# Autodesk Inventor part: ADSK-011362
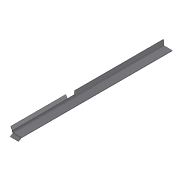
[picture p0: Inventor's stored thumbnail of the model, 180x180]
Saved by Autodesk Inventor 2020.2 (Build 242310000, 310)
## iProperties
Created: 1999-12
Part Number: ADSK-011362
Material: 1.0312 DC05
Document SubType Name: Tôlerie
Designer: sspink
Density: 1 g/cm^3
Sheet Metal Rule: Stahlblech 1.0312 - DC05 -   3.0 mm
Appearance: Metal-Steel(Polish)
Mass: 343.254 g
Surface Area: 2364.73 cm^2
Volume: 343.254 cm^3
Sheet Metal Width: 102,290 mm
Sheet Metal Length: 1142,047 mm
Sheet Metal Area: 116819,823 mm^2
Flat Pattern Width: 10.229 cm
Flat Pattern Length: 114.205 cm
Flat Pattern Area: 1168.2 cm^2
Control State: 0
Checked Out: False
Master: False
Shininess: 57.0
Length Units: 11269
Angle Units: 11279
Time Units: 11290
Mass Units: 11283
Length Display Precision: 3
Angle Display Precision: 2
Compacted: True
CUTLENGTH: 3.81 X 45.03 (172 SI)
MATERIAL DESC: SHEET,S/S, 11 GA
MATERIAL_NUMBER: A084638
G_L: 102,3x1142 mm
Thickness: 3,000 mm
Dimensions: 53,1x1139,7x78,7 mm
Mass: 0,343 kg
Semi finished: Stahlblech 1.0312 - DC05 -   3.0 mm
VLT_Material: 1.0312 DC05
Density: 8.03
Volumn: 355.19187961954367
Area: 2316.6606297786716
PropertySet Name: Model Information
Author: sspink
Revision Number: -
Title: ADSK-011362
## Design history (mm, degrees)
node "Solide1"
  node "Konturlasche1"
  node "Lasche1"
  node "Lasche2"
sketch "Sketch1"
  geometry: L1 (0, 0)-(63.5, 0); 1 further point; 1 other entity
  constraints: 2 end point, 1 horizontal, 3 other
  dimensions: "d3" = 38 distance of L1.start point (-0.092, 38); "d58" = 63.5 distance of L1.start L1.end
feature "Biegung5" dims "d57" = 3 (derived), "d69" = 3 (derived), "d70" = 1.5 (derived), "d71" = 6 (derived), "d72" = 3 (derived), "d73" = 25, "d74" = 30 deg, "d75" = 3 (derived), "SeamGap" = 0.00508
feature "Ecke2" dims "d73" = 25, "d74" = 30 deg, "d76" = 12 (derived), "d77" = 3 (derived), "d78" = 3 (derived)
sketch "Skizze14"
  geometry: L1 (-3, 0)-(-3, 1118) reference; L2 (2.993, 1118)-(2.993, 1.608) reference; L3 (-3, 0)-(2.993, 0); L4 (2.993, 0)-(2.993, 1.608); L5 (-3, 460)-(2.993, 460); 1 further point
  constraints: 6 end point, 2 perpendicular, 2 point on line, 1 horizontal
  dimensions: "d82" = 460 distance between parallel lines of L3 L5
feature "Ausklinkung2" dims "d83" = 25, "d84" = 0
sketch "Skizze15"
  geometry: L1 (0, 460)-(0, 54); L2 (0, 54)-(25, 54); L3 (25, 54)-(25, 460); L4 (25, 460)-(0, 460)
  constraints: 8 end point
feature "Grobblech3" dims "d57" = 3 (derived), "d85" = 3 (derived), "d86" = 1.5 (derived), "d87" = 6 (derived), "d88" = 3 (derived), "d89" = 25, "d90" = 30 deg, "d91" = 3 (derived), "d92" = 12 (derived), "d93" = 3 (derived), "d94" = 3 (derived), "d95" = 406, "d96" = 0, "SeamGap" = 0.00508
feature "Biegung6" dims "d57" = 3 (derived), "d85" = 3 (derived), "d86" = 1.5 (derived), "d87" = 6 (derived), "d88" = 3 (derived), "d89" = 25, "d90" = 30 deg, "d91" = 3 (derived), "SeamGap" = 0.00508
feature "Ecke3" dims "d89" = 25, "d90" = 30 deg, "d92" = 12 (derived), "d93" = 3 (derived), "d94" = 3 (derived)
feature "Grobblech1" dims "d57" = 3 (derived), "d59" = 3 (derived), "d60" = 1.5 (derived), "d61" = 6 (derived), "d62" = 3 (derived), "d63" = 1118, "d64" = 3 (derived), "d65" = 3, "d66" = 12 (derived), "d67" = 3 (derived), "d68" = 3 (derived), "SeamGap" = 0.00508
feature "Biegung4" dims "d57" = 3 (derived), "d59" = 3 (derived), "d60" = 1.5 (derived), "d61" = 6 (derived), "d62" = 3 (derived), "d64" = 3 (derived), "d65" = 3, "SeamGap" = 0.00508
feature "Ecke1" dims "d65" = 3, "d66" = 12 (derived), "d67" = 3 (derived), "d68" = 3 (derived)
sketch "Skizze12"
  geometry: L1 through (-30.254, 0) direction (1, -4.98e-18); L2 through (0, 12.5) direction (-1.5e-17, 1); L3 (0, 25)-(-60.507, 25); L4 (-60.507, 25)-(-60.507, 0)
  constraints: 6 end point, 1 horizontal, 1 perpendicular, 1 vertical
feature "Grobblech2" dims "d57" = 3 (derived), "d69" = 3 (derived), "d70" = 1.5 (derived), "d71" = 6 (derived), "d72" = 3 (derived), "d73" = 25, "d74" = 30 deg, "d75" = 3 (derived), "d76" = 12 (derived), "d77" = 3 (derived), "d78" = 3 (derived), "SeamGap" = 0.00508
node "Corps solides"
node "Corps surfaciques"
feature "Definition1"
other parameters: "Thickness" = 3 (derived), "BendRadius" = 3 (derived), "BendReliefWidth" = 3 (derived), "BendReliefDepth" = 1.5 (derived), "CornerReliefSize" = 12 (derived), "MinimumRemnant" = 6 (derived), "TransitionRadius" = 3 (derived), "TailleRayonJacobi" = 3 (derived), "TailleJeu" = 3 (derived), "BendRadius" = 3, "BendReliefDepth" = 1.5, "BendReliefWidth" = 3, "CornerReliefSize" = 12, "MinimumRemnant" = 6, "TailleJeu" = 3, "TailleRayonJacobi" = 3, "Thickness" = 3, "TransitionRadius" = 3
